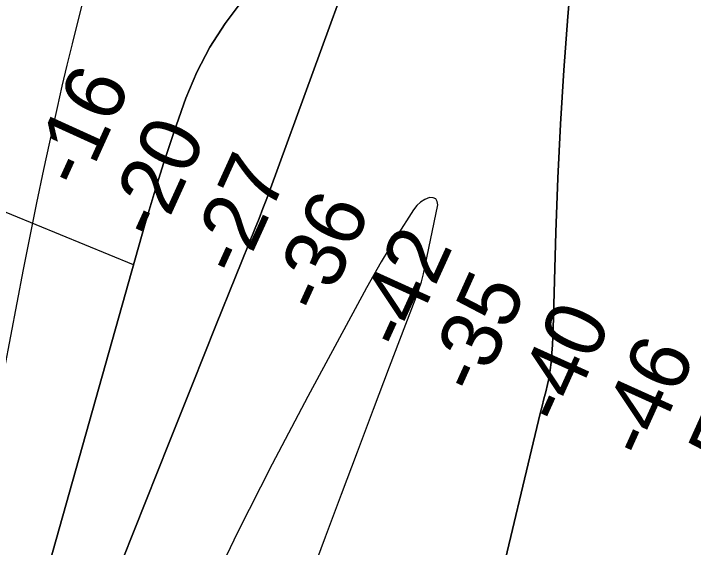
# Model space of a CAD drawing. Extents: x 3925854 to 3964121, y 224593 to 250589.
# Drawn here: x 3942850 to 3943605, y 238574 to 239167 of the extents above; entities that cross this region are included whole.
import ezdxf

# ---------------------------------------------------------------- set-up
doc = ezdxf.new("R2010")
doc.units = 0
for name, color, linetype in [('V-RIVR-RANG', 7, 'Continuous'), ('V-TOPO-DPTH', 7, 'Continuous'), ('V-TOPO-MINR', 7, 'Continuous')]:
    doc.layers.add(name, color=color, linetype=linetype)

msp = doc.modelspace()

# ---------------------------------------------------------------- linework, layer by layer
at = {"layer": 'V-TOPO-DPTH'}
for points in [[(3942983.62, 238887.801), (3942658.91, 239021.11), (3942869.48, 240055.28), (3942865.529, 240782.275), (3942865.271, 240811.75), (3942864.883, 240841.222), (3942864.3, 240870.691), (3942863.587, 240900.157), (3942843.55, 241628.53), (3943150.608, 241695.11)], [(3942857.385, 238439.744), (3942996.497, 238933.506), (3943006.352, 238967.022), (3943016.712, 239000.375), (3943027.827, 239033.484), (3943039.446, 239066.431), (3943041.7, 239072.597), (3943054.014, 239101.504), (3943068.207, 239129.326), (3943085.216, 239155.522), (3943104.103, 239180.633), (3943127.445, 239208.507), (3943135.429, 239219.224), (3943142.538, 239230.428), (3943148.335, 239242.365), (3943153.258, 239254.789), (3943158.725, 239271.268), (3943160.041, 239275.866), (3943161.097, 239280.512), (3943161.763, 239285.23), (3943162.17, 239289.995), (3943184.158, 239795.586), (3943186.145, 239840.255), (3943188.192, 239884.921)], [(3943188.192, 239884.921), (3943186.145, 239840.255), (3943184.158, 239795.586), (3943162.17, 239289.995), (3943161.763, 239285.23), (3943161.097, 239280.512), (3943160.041, 239275.866), (3943158.725, 239271.268), (3943153.258, 239254.789), (3943148.335, 239242.365), (3943142.538, 239230.428), (3943135.429, 239219.224), (3943127.445, 239208.507), (3943104.103, 239180.633), (3943085.216, 239155.522), (3943068.207, 239129.326), (3943054.014, 239101.504), (3943041.7, 239072.597), (3943039.446, 239066.431), (3943027.827, 239033.484), (3943016.712, 239000.375), (3943006.352, 238967.022), (3942996.497, 238933.506), (3942983.62, 238887.801)], [(3943473.873, 239258.346), (3943465.987, 239163.525), (3943461.504, 239103.73), (3943457.67, 239043.899), (3943454.809, 238984.014), (3943452.597, 238924.092), (3943449.509, 238816.798), (3943449.167, 238807.802), (3943448.713, 238798.812), (3943448.092, 238789.832), (3943447.359, 238780.859), (3943447.231, 238779.447), (3943446.268, 238771.223), (3943445.024, 238763.049), (3943443.361, 238754.95), (3943441.416, 238746.901), (3943439.296, 238738.881), (3943437.222, 238730.849), (3943435.219, 238722.8), (3943433.263, 238714.738), (3943387.141, 238520.986)], [(3943387.141, 238520.986), (3943433.263, 238714.738), (3943435.219, 238722.8), (3943437.222, 238730.849), (3943439.296, 238738.881), (3943441.416, 238746.901), (3943443.361, 238754.95), (3943445.024, 238763.049), (3943446.268, 238771.223), (3943447.231, 238779.447), (3943447.359, 238780.859), (3943448.092, 238789.832), (3943448.713, 238798.812), (3943449.167, 238807.802), (3943449.509, 238816.798), (3943452.597, 238924.092), (3943454.809, 238984.014), (3943457.67, 239043.899), (3943461.504, 239103.73), (3943465.987, 239163.525), (3943473.873, 239258.346)], [(3943229.868, 239230.529), (3943135.541, 238972.425), (3943131.436, 238961.359), (3943127.259, 238950.321), (3943122.975, 238939.325), (3943118.619, 238928.355), (3943075.113, 238820.332), (3943049.021, 238755.343), (3943023.022, 238690.318), (3942997.163, 238625.236), (3942971.398, 238560.117)], [(3942971.398, 238560.117), (3942997.163, 238625.236), (3943023.022, 238690.318), (3943049.021, 238755.343), (3943075.113, 238820.332), (3943118.619, 238928.355), (3943122.975, 238939.325), (3943127.259, 238950.321), (3943131.436, 238961.359), (3943135.541, 238972.425), (3943229.868, 239230.529)], [(3943052.616, 238198.007), (3943196.816, 238585.863), (3943214.454, 238633.105), (3943232.177, 238680.314), (3943250.029, 238727.474), (3943267.967, 238774.602), (3943297.511, 238851.904), (3943300.527, 238860.419), (3943303.257, 238869.017), (3943305.559, 238877.74), (3943307.576, 238886.545), (3943321.346, 238954.322), (3943320.721, 238958.165), (3943319.164, 238960.982)], [(3943052.616, 238198.007), (3943196.816, 238585.863), (3943214.454, 238633.105), (3943232.177, 238680.314), (3943250.029, 238727.474), (3943267.967, 238774.602), (3943297.511, 238851.904), (3943300.527, 238860.419), (3943303.257, 238869.017), (3943305.559, 238877.74), (3943307.576, 238886.545), (3943321.346, 238954.322), (3943320.721, 238958.165), (3943319.164, 238960.982)], [(3943319.164, 238960.982), (3943316.21, 238962.26), (3943312.325, 238962.512), (3943307.034, 238960.237), (3943302.23, 238957.325), (3943298.155, 238953.457), (3943294.567, 238948.952), (3943275.765, 238919.199), (3943267.093, 238905.162), (3943258.614, 238891.011), (3943250.424, 238876.691), (3943242.428, 238862.258), (3943177.197, 238741.634), (3943137.594, 238666.378), (3943099.14, 238590.556), (3943062.41, 238513.884)], [(3943319.164, 238960.982), (3943316.21, 238962.26), (3943312.325, 238962.512), (3943307.034, 238960.237), (3943302.23, 238957.325), (3943298.155, 238953.457), (3943294.567, 238948.952), (3943275.765, 238919.199), (3943267.093, 238905.162), (3943258.614, 238891.011), (3943250.424, 238876.691), (3943242.428, 238862.258), (3943177.197, 238741.634), (3943137.594, 238666.378), (3943099.14, 238590.556), (3943062.41, 238513.884)]]:
    msp.add_lwpolyline(points, dxfattribs=at)
at = {"layer": 'V-TOPO-MINR'}
for points in [[(3943188.192, 239884.921), (3943186.145, 239840.255), (3943184.158, 239795.586), (3943162.17, 239289.995), (3943161.763, 239285.23), (3943161.097, 239280.512), (3943160.041, 239275.866), (3943158.725, 239271.268), (3943153.258, 239254.789), (3943148.335, 239242.365), (3943142.538, 239230.428), (3943135.429, 239219.224), (3943127.445, 239208.507), (3943104.103, 239180.633), (3943085.216, 239155.522), (3943068.207, 239129.326), (3943054.014, 239101.504), (3943041.7, 239072.597), (3943039.446, 239066.431), (3943027.827, 239033.484), (3943016.712, 239000.375), (3943006.352, 238967.022), (3942996.497, 238933.506), (3942857.385, 238439.744)], [(3943473.873, 239258.346), (3943465.987, 239163.525), (3943461.504, 239103.73), (3943457.67, 239043.899), (3943454.809, 238984.014), (3943452.597, 238924.092), (3943449.509, 238816.798), (3943449.167, 238807.802), (3943448.713, 238798.812), (3943448.092, 238789.832), (3943447.359, 238780.859), (3943447.231, 238779.447), (3943446.268, 238771.223), (3943445.024, 238763.049), (3943443.361, 238754.95), (3943441.416, 238746.901), (3943439.296, 238738.881), (3943437.222, 238730.849), (3943435.219, 238722.8), (3943433.263, 238714.738), (3943387.141, 238520.986)], [(3942939.23, 239228.42), (3942915.275, 239132.917), (3942909.521, 239109.482), (3942903.926, 239086.01), (3942898.567, 239062.482), (3942893.366, 239038.918), (3942883.608, 238993.627), (3942875.815, 238956.697), (3942868.23, 238919.725), (3942860.959, 238882.689), (3942853.897, 238845.612), (3942846.881, 238808.525), (3942839.719, 238771.467), (3942832.337, 238734.452), (3942824.808, 238697.466), (3942803.99, 238596.722), (3942792.709, 238544.741)], [(3943229.868, 239230.529), (3943135.541, 238972.425), (3943131.436, 238961.359), (3943127.259, 238950.321), (3943122.975, 238939.325), (3943118.619, 238928.355), (3943075.113, 238820.332), (3943049.021, 238755.343), (3943023.022, 238690.318), (3942997.163, 238625.236), (3942971.398, 238560.117)], [(3943052.616, 238198.007), (3943196.816, 238585.863), (3943214.454, 238633.105), (3943232.177, 238680.314), (3943250.029, 238727.474), (3943267.967, 238774.602), (3943297.511, 238851.904), (3943300.527, 238860.419), (3943303.257, 238869.017), (3943305.559, 238877.74), (3943307.576, 238886.545), (3943321.346, 238954.322), (3943320.721, 238958.165), (3943319.164, 238960.982)], [(3943319.164, 238960.982), (3943316.21, 238962.26), (3943312.325, 238962.512), (3943307.034, 238960.237), (3943302.23, 238957.325), (3943298.155, 238953.457), (3943294.567, 238948.952), (3943275.765, 238919.199), (3943267.093, 238905.162), (3943258.614, 238891.011), (3943250.424, 238876.691), (3943242.428, 238862.258), (3943177.197, 238741.634), (3943137.594, 238666.378), (3943099.14, 238590.556), (3943062.41, 238513.884)]]:
    msp.add_lwpolyline(points, dxfattribs=at)

# ---------------------------------------------------------------- texts
at = {"layer": 'V-RIVR-RANG'}
for s, rotation, p in [('-16', 65.578326, (3942927.395, 238969.518)), ('-20', 65.578326, (3943011.241, 238912.302)), ('-27', 65.578326, (3943102.721, 238871.898)), ('-36', 65.578326, (3943193.655, 238830.294)), ('-42', 65.578326, (3943285.244, 238790.131)), ('-35', 65.717472, (3943367.139, 238740.906)), ('-40', 65.717472, (3943461.457, 238706.934)), ('-46', 65.717472, (3943554.719, 238669.404)), ('-50', 65.717472, (3943645.722, 238628.814))]:
    msp.add_text(s, height=67, rotation=rotation, dxfattribs=at).set_placement(p)

doc.saveas('drawing.dxf')
